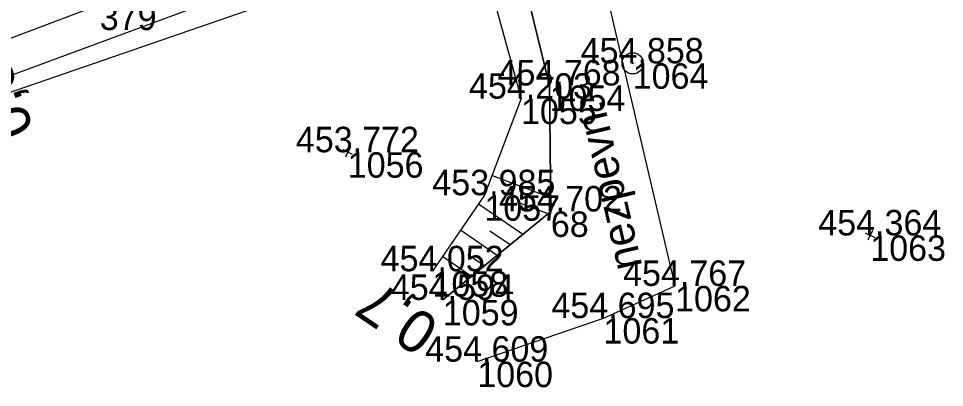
# Model space of a CAD drawing. Extents: x -751615 to -750797, y -1114905 to -1114561.
# Drawn here: x -751550.15 to -751506.5, y -1114848.3 to -1114830.9 of the extents above; entities that cross this region are included whole.
import ezdxf

# ---------------------------------------------------------------- set-up
doc = ezdxf.new("R2010")
doc.units = 0
for name, color, linetype in [('Vrstva 48', 7, 'Continuous'), ('Vrstva 49', 7, 'Continuous'), ('Vrstva 51', 7, 'Continuous'), ('Vrstva 53', 7, 'Continuous'), ('Vrstva 60', 7, 'Continuous'), ('Vrstva 61', 7, 'Continuous')]:
    doc.layers.add(name, color=color, linetype=linetype)

msp = doc.modelspace()

# ---------------------------------------------------------------- linework, layer by layer
at = {"layer": 'Vrstva 48'}
for p, q in [((-751525.064, -1114839.349), (-751527.836, -1114838.299)), ((-751525.189, -1114840.104), (-751526.645, -1114839.552)), ((-751526.377, -1114841.077), (-751528.473, -1114839.647)), ((-751527.586, -1114842.067), (-751529.318, -1114840.886)), ((-751526.981, -1114841.572), (-751527.938, -1114840.919)), ((-751528.796, -1114843.058), (-751530.163, -1114842.125)), ((-751528.191, -1114842.563), (-751528.966, -1114842.034))]:
    msp.add_line(p, q, dxfattribs=at)
at = {"layer": 'Vrstva 49'}
for p, q in [((-751534.993, -1114829.012), (-751582.438, -1114845.392)), ((-751534.405, -1114837.315), (-751534.855, -1114837.095)), ((-751534.52, -1114836.98), (-751534.74, -1114837.43)), ((-751509.776, -1114841.235), (-751510.226, -1114841.017)), ((-751509.892, -1114840.901), (-751510.11, -1114841.351))]:
    msp.add_line(p, q, dxfattribs=at)
for points in [[(-751530.15, -1114844.167), (-751525.058, -1114839.997), (-751525.116, -1114834.058), (-751526.946, -1114826.6), (-751528.668, -1114821.908)], [(-751586.983, -1114844.483), (-751566.691, -1114837.92), (-751546.322, -1114830.244), (-751529.778, -1114824.115), (-751528.71, -1114826.495)], [(-751528.71, -1114826.495), (-751526.464, -1114834.679), (-751528.189, -1114839.231), (-751530.635, -1114842.817)], [(-751535.416, -1114827.991), (-751582.438, -1114845.392)]]:
    msp.add_lwpolyline(points, dxfattribs=at)
at = {"layer": 'Vrstva 51'}
for points in [[(-751519.201, -1114843.506), (-751523.621, -1114824.567), (-751524.266, -1114822.243), (-751525.072, -1114820.521), (-751528.668, -1114821.908), (-751526.946, -1114826.6), (-751525.116, -1114834.058), (-751525.058, -1114839.997), (-751530.15, -1114844.167)], [(-751528.526, -1114847.078), (-751522.576, -1114845.026), (-751519.201, -1114843.506)]]:
    msp.add_lwpolyline(points, dxfattribs=at)
at = {"layer": 'Vrstva 53'}
msp.add_line((-751521.152, -1114832.999), (-751521.246, -1114833.031), dxfattribs=at)
msp.add_circle((-751521.199, -1114833.015), 0.499, dxfattribs=at)
at = {"layer": 'Vrstva 60'}
for p, q in [((-751521.199, -1114833.015), (-751521.199, -1114833.015)), ((-751525.116, -1114834.058), (-751525.116, -1114834.058)), ((-751526.464, -1114834.679), (-751526.464, -1114834.679)), ((-751534.63, -1114837.205), (-751534.63, -1114837.205)), ((-751528.189, -1114839.231), (-751528.189, -1114839.231)), ((-751525.058, -1114839.997), (-751525.058, -1114839.997)), ((-751510.001, -1114841.126), (-751510.001, -1114841.126)), ((-751530.635, -1114842.817), (-751530.635, -1114842.817)), ((-751519.201, -1114843.506), (-751519.201, -1114843.506)), ((-751530.15, -1114844.167), (-751530.15, -1114844.167)), ((-751522.576, -1114845.026), (-751522.576, -1114845.026)), ((-751528.526, -1114847.078), (-751528.526, -1114847.078))]:
    msp.add_line(p, q, dxfattribs=at)

# ---------------------------------------------------------------- texts
at = {"layer": 'Vrstva 48'}
for s, rotation, p in [('0,3', 110.3075, (-751549.402, -1114836.169)), ('0,7', 145.7022, (-751530.204, -1114845.237))]:
    msp.add_text(s, height=2, rotation=rotation, dxfattribs=at).set_placement(p)
at = {"layer": 'Vrstva 51'}
msp.add_text('nezpevn.', height=1.5, rotation=103.1366, dxfattribs=at).set_placement((-751520.741, -1114842.573))
at = {"layer": 'Vrstva 60'}
for s, p in [('379', (-751546.322, -1114831.444)), ('1064', (-751521.199, -1114834.215)), ('1054', (-751525.116, -1114835.258)), ('1055', (-751526.464, -1114835.879)), ('1056', (-751534.63, -1114838.405)), ('1057', (-751528.189, -1114840.431)), ('68', (-751525.058, -1114841.197)), ('1063', (-751510.001, -1114842.326)), ('1058', (-751530.635, -1114844.017)), ('1062', (-751519.201, -1114844.706)), ('1059', (-751530.15, -1114845.367)), ('1061', (-751522.576, -1114846.226)), ('1060', (-751528.526, -1114848.278))]:
    msp.add_text(s, height=1.2, dxfattribs=at).set_placement(p)
at = {"layer": 'Vrstva 61'}
for s, p in [('454.858', (-751523.653, -1114833.015)), ('454.768', (-751527.57, -1114834.058)), ('454.203', (-751528.916, -1114834.679)), ('453.772', (-751537.078, -1114837.205)), ('453.985', (-751530.645, -1114839.231)), ('454.702', (-751527.506, -1114839.997)), ('454.364', (-751512.452, -1114841.126)), ('454.052', (-751533.083, -1114842.817)), ('454.767', (-751521.653, -1114843.506)), ('454.594', (-751532.601, -1114844.167)), ('454.695', (-751525.032, -1114845.026)), ('454.609', (-751530.98, -1114847.078))]:
    msp.add_text(s, height=1.2, dxfattribs=at).set_placement(p)

doc.saveas('drawing.dxf')
